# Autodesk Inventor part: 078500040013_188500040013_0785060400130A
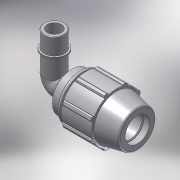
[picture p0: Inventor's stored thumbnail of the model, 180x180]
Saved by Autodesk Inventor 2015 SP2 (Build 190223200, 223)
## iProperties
Created: 2017-02
Part Number: 078500040013_188500040013_0785060400130A
Material: PVC-Piping
Description: PLASSON 90° ELBOW MALE ADAPTOR 40-1.1/4"
Document SubType Name: Modeling
Designer: KIM
Mass: 92.6774 g
Surface Area: 199.44 cm^2
Volume: 66.1981 cm^3
Density: 1.4 g/cm^3
Appearance: Smooth - White
Author: KIM
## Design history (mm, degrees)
derived "07850.ipt"
feature "Solid1::07850.ipt"
tag "TaggingFeature1"
body "Solid1"
other parameters: "d4" = 10.33333, "d5" = 31, "d7" = 82, "d9" = 17.71429, "d11" = 4.13333, "d13" = 120 deg, "d14" = 56, "d15" = 12 deg, "d16" = 71.34, "d18" = 2, "d19" = 35 deg, "d20" = 17.5 deg, "d21" = 76.26, "d23" = 0, "d25" = 360 deg, "d27" = 1.64, "d33" = 0.8, "d42" = 45.88, "d43" = 2.46, "d46" = 1.2, "d51" = 124, "d68" = 4.13333, "d72" = 66, "d73" = 41.91, "d74" = 22, "d75" = 48.1965, "d76" = 29.337, "d77" = 24.2, "d79" = 16.764, "d80" = 1.2573, "d83" = 0, "d84" = 0, "d91" = 61.5, "d93" = 84, "d94" = 41.91, "d95" = 29.337, "d96" = 12.4, "d97" = 50 deg, "E_" = 82, "A_" = 124, "l_" = 84, "l_2" = 22, "A_1" = 66, "R_" = 41.91
